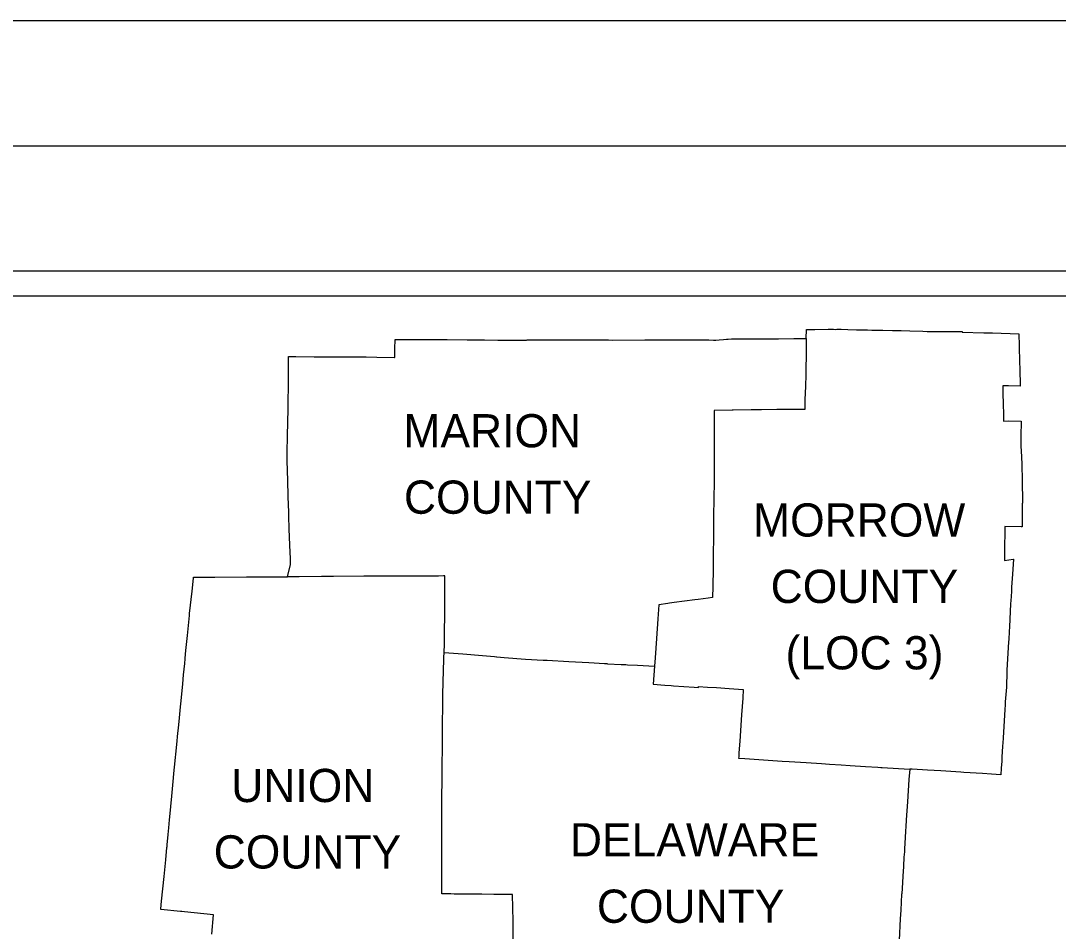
# Model space of a CAD drawing. Extents: x 0 to 34, y 0 to 22.
# Drawn here: x 3.544 to 7.693, y 18.358 to 22 of the extents above; entities that cross this region are included whole.
import ezdxf

# ---------------------------------------------------------------- set-up
doc = ezdxf.new("R2010")
doc.units = 0
for name, color, linetype in [('GM_X_County', 7, 'Continuous'), ('SH_Border', 7, 'Continuous'), ('SH_Cut_Line', 7, 'Continuous'), ('SH_Data', 7, 'Continuous')]:
    doc.layers.add(name, color=color, linetype=linetype)

msp = doc.modelspace()

# ---------------------------------------------------------------- linework, layer by layer
at = {"layer": 'GM_X_County'}
for p, q in [((6.6856, 20.7295), (6.6866, 20.7654)), ((6.6866, 20.7654), (6.7195, 20.7656)), ((6.7195, 20.7656), (6.7729, 20.7658)), ((6.7729, 20.7658), (6.7945, 20.7658)), ((6.7945, 20.7658), (6.803, 20.7656)), ((6.803, 20.7656), (6.8079, 20.7658)), ((6.8079, 20.7658), (6.8254, 20.766)), ((6.8254, 20.766), (6.8515, 20.7651)), ((6.8515, 20.7651), (6.886, 20.7639)), ((6.886, 20.7639), (6.8953, 20.7638)), ((6.8953, 20.7638), (6.9269, 20.7633)), ((6.9269, 20.7633), (6.9307, 20.7631)), ((6.9307, 20.7631), (6.9473, 20.7629)), ((6.9473, 20.7629), (6.9532, 20.7628)), ((6.9532, 20.7628), (6.9634, 20.7628)), ((6.9634, 20.7628), (6.9922, 20.7622)), ((6.9922, 20.7622), (7.0299, 20.7614)), ((7.0299, 20.7614), (7.0649, 20.7604)), ((7.0649, 20.7604), (7.1, 20.7596)), ((7.1, 20.7596), (7.1524, 20.7582)), ((7.1524, 20.7582), (7.1695, 20.7575)), ((7.1695, 20.7575), (7.1866, 20.7571)), ((7.1866, 20.7571), (7.2147, 20.7565)), ((7.2147, 20.7565), (7.3093, 20.7565)), ((7.3093, 20.7565), (7.3093, 20.7542)), ((7.3093, 20.7542), (7.3951, 20.752)), ((7.3951, 20.752), (7.4302, 20.7511)), ((7.4302, 20.7511), (7.5362, 20.7483)), ((7.5362, 20.7483), (7.5371, 20.6992)), ((5.0405, 20.6879), (5.0411, 20.725)), ((5.0411, 20.725), (5.0621, 20.7251)), ((5.0621, 20.7251), (5.1848, 20.725)), ((5.1848, 20.725), (5.2501, 20.7247)), ((5.2501, 20.7247), (5.329, 20.7243)), ((5.329, 20.7243), (5.3818, 20.7231)), ((5.3818, 20.7231), (5.3901, 20.7232)), ((5.3901, 20.7232), (5.3993, 20.723)), ((5.3993, 20.723), (5.4521, 20.7223)), ((5.4521, 20.7223), (5.4693, 20.7224)), ((5.4693, 20.7224), (5.5416, 20.7227)), ((5.5416, 20.7227), (5.567, 20.7229)), ((5.567, 20.7229), (5.5697, 20.723)), ((5.5697, 20.723), (5.5794, 20.7231)), ((5.5794, 20.7231), (5.6115, 20.7233)), ((5.6115, 20.7233), (5.6401, 20.7234)), ((5.6401, 20.7234), (5.6827, 20.7237)), ((5.6827, 20.7237), (5.753, 20.724)), ((5.753, 20.724), (5.8235, 20.7233)), ((5.8235, 20.7233), (5.8261, 20.7233)), ((5.8261, 20.7233), (5.8298, 20.7232)), ((5.8298, 20.7232), (5.8419, 20.7232)), ((5.8419, 20.7232), (5.8941, 20.7231)), ((5.8941, 20.7231), (5.9122, 20.7229)), ((5.9122, 20.7229), (6.0406, 20.7231)), ((6.0406, 20.7231), (6.1476, 20.7233)), ((6.1476, 20.7233), (6.2484, 20.7238)), ((6.2484, 20.7238), (6.2963, 20.723)), ((6.2963, 20.723), (6.3143, 20.7226)), ((6.3143, 20.7226), (6.3191, 20.7226)), ((6.3191, 20.7226), (6.3236, 20.7228)), ((6.3236, 20.7228), (6.3375, 20.7237)), ((6.3375, 20.7237), (6.3545, 20.725)), ((6.3545, 20.725), (6.3662, 20.7259)), ((6.3662, 20.7259), (6.3728, 20.7263)), ((6.3728, 20.7263), (6.3872, 20.7275)), ((6.3872, 20.7275), (6.3891, 20.7276)), ((6.3891, 20.7276), (6.4254, 20.7277)), ((6.4254, 20.7277), (6.4621, 20.7274)), ((6.4621, 20.7274), (6.4892, 20.7279)), ((6.4892, 20.7279), (6.4913, 20.728)), ((6.4913, 20.728), (6.4973, 20.728)), ((6.4973, 20.728), (6.5516, 20.7282)), ((6.5516, 20.7282), (6.5752, 20.7283)), ((6.5752, 20.7283), (6.6354, 20.7289)), ((6.6354, 20.7289), (6.6595, 20.7292)), ((6.6595, 20.7292), (6.6856, 20.7295)), ((6.6856, 20.7295), (6.6853, 20.6951)), ((5.04, 20.6537), (5.0405, 20.6879)), ((6.6853, 20.6951), (6.6847, 20.6432)), ((7.5371, 20.6992), (7.5389, 20.6325)), ((4.6151, 20.6558), (4.6152, 20.6569)), ((4.6151, 20.652), (4.6151, 20.6558)), ((4.6153, 20.6358), (4.6151, 20.652)), ((4.6152, 20.6569), (4.6438, 20.6567)), ((4.6152, 20.5873), (4.6153, 20.6358)), ((4.6438, 20.6567), (4.7179, 20.6562)), ((4.7179, 20.6562), (4.7573, 20.656)), ((4.7573, 20.656), (4.8279, 20.656)), ((4.8279, 20.656), (4.899, 20.6556)), ((4.899, 20.6556), (4.9257, 20.6554)), ((4.9257, 20.6554), (4.9685, 20.6545)), ((4.9685, 20.6545), (5.0394, 20.6529)), ((5.0394, 20.6529), (5.04, 20.6529)), ((5.04, 20.6529), (5.04, 20.6537)), ((6.6845, 20.6263), (6.6841, 20.5852)), ((6.6847, 20.6432), (6.6845, 20.6263)), ((7.5389, 20.6325), (7.5396, 20.6085)), ((4.6149, 20.534), (4.6152, 20.5873)), ((6.6841, 20.5823), (6.6829, 20.5394)), ((6.6841, 20.5852), (6.6841, 20.5823)), ((7.5396, 20.6085), (7.5412, 20.5388)), ((6.6829, 20.5394), (6.6828, 20.5379)), ((7.4947, 20.5397), (7.4719, 20.5401)), ((7.4719, 20.5401), (7.4724, 20.5242)), ((7.5412, 20.5388), (7.4947, 20.5397)), ((4.6142, 20.4815), (4.6149, 20.534)), ((6.6828, 20.5379), (6.6796, 20.4842)), ((7.4724, 20.5242), (7.4722, 20.5102)), ((7.4722, 20.5102), (7.4722, 20.5091)), ((7.4722, 20.5091), (7.4731, 20.4672)), ((4.6134, 20.4465), (4.6142, 20.4815)), ((6.6796, 20.4842), (6.6794, 20.4454)), ((7.4731, 20.4672), (7.474, 20.4249)), ((4.6106, 20.3414), (4.6134, 20.4465)), ((6.3888, 20.4424), (6.3171, 20.441)), ((6.3171, 20.441), (6.3172, 20.4059)), ((6.3927, 20.4425), (6.3888, 20.4424)), ((6.4647, 20.4432), (6.3927, 20.4425)), ((6.4769, 20.4434), (6.4647, 20.4432)), ((6.482, 20.4435), (6.4769, 20.4434)), ((6.5063, 20.444), (6.482, 20.4435)), ((6.5685, 20.4447), (6.5063, 20.444)), ((6.603, 20.4451), (6.5685, 20.4447)), ((6.6383, 20.4454), (6.603, 20.4451)), ((6.6794, 20.4454), (6.6383, 20.4454)), ((7.474, 20.4249), (7.4745, 20.3989)), ((6.3172, 20.4059), (6.3172, 20.3947)), ((6.3172, 20.3947), (6.3173, 20.3712)), ((7.4745, 20.3989), (7.4952, 20.3991)), ((7.4952, 20.3991), (7.5454, 20.3989)), ((7.5454, 20.3989), (7.5444, 20.3365)), ((4.6101, 20.2718), (4.6106, 20.3414)), ((6.3173, 20.3435), (6.3172, 20.2998)), ((6.3173, 20.3712), (6.3173, 20.3435)), ((7.5444, 20.3365), (7.5443, 20.3345)), ((7.5443, 20.3345), (7.5443, 20.3204)), ((6.3172, 20.2998), (6.317, 20.2299)), ((7.5443, 20.3204), (7.5444, 20.2979)), ((7.5444, 20.2979), (7.5459, 20.2576)), ((4.61, 20.2358), (4.6101, 20.2708)), ((4.6101, 20.2708), (4.6101, 20.2718)), ((7.5459, 20.2576), (7.5473, 20.2239)), ((4.6104, 20.2048), (4.61, 20.2358)), ((6.317, 20.2299), (6.3168, 20.1568)), ((7.5473, 20.2239), (7.5487, 20.1629)), ((4.6137, 20.1056), (4.6104, 20.2048)), ((6.3168, 20.1568), (6.3153, 20.0187)), ((7.5487, 20.1629), (7.549, 20.153)), ((7.549, 20.153), (7.5507, 20.0826)), ((4.6143, 20.0864), (4.6137, 20.1056)), ((4.6146, 20.0742), (4.6143, 20.0864)), ((7.5507, 20.0826), (7.5508, 20.079)), ((4.6147, 20.073), (4.6146, 20.0742)), ((4.6159, 20.0266), (4.6147, 20.073)), ((7.5496, 20.0597), (7.5495, 20.0116)), ((7.5499, 20.0717), (7.5496, 20.0678)), ((7.5496, 20.0678), (7.5496, 20.0631)), ((7.5496, 20.0631), (7.5496, 20.0597)), ((7.55, 20.0727), (7.5499, 20.0717)), ((7.5503, 20.0735), (7.55, 20.0727)), ((7.5506, 20.074), (7.5503, 20.0735)), ((7.5508, 20.079), (7.5506, 20.074)), ((4.616, 20.0228), (4.6159, 20.0266)), ((4.6162, 20.0178), (4.616, 20.0228)), ((4.6179, 19.9678), (4.6162, 20.0178)), ((6.3153, 20.0187), (6.3146, 19.9478)), ((7.5495, 20.0116), (7.5497, 19.9808)), ((4.6203, 19.902), (4.6179, 19.9678)), ((7.5453, 19.9759), (7.4791, 19.9766)), ((7.4791, 19.9766), (7.4791, 19.9708)), ((7.4791, 19.9708), (7.4791, 19.945)), ((7.5497, 19.9759), (7.5453, 19.9759)), ((7.5497, 19.9808), (7.5497, 19.9759)), ((6.3146, 19.9478), (6.3135, 19.8521)), ((7.4791, 19.945), (7.479, 19.9046)), ((4.6225, 19.8473), (4.6203, 19.902)), ((7.479, 19.9046), (7.4788, 19.8413)), ((4.6234, 19.8253), (4.6225, 19.8473)), ((6.3135, 19.8521), (6.3128, 19.8072)), ((7.4788, 19.8413), (7.5127, 19.8457)), ((7.5145, 19.8458), (7.5105, 19.7867)), ((7.5127, 19.8457), (7.5145, 19.8458)), ((4.6114, 19.7761), (4.6234, 19.8253)), ((6.3128, 19.8072), (6.3116, 19.737)), ((4.2291, 19.7189), (4.2348, 19.7709)), ((4.2348, 19.7709), (4.2352, 19.7745)), ((4.2352, 19.7745), (4.2355, 19.7745)), ((4.2355, 19.7745), (4.3101, 19.7744)), ((4.3101, 19.7744), (4.3201, 19.7745)), ((4.3201, 19.7745), (4.4466, 19.7751)), ((4.4466, 19.7751), (4.4939, 19.7753)), ((4.4939, 19.7753), (4.5443, 19.7756)), ((4.5443, 19.7756), (4.6114, 19.7761)), ((4.6572, 19.7763), (4.6114, 19.7761)), ((4.7464, 19.7766), (4.6572, 19.7763)), ((4.7722, 19.7767), (4.7464, 19.7766)), ((4.7947, 19.7769), (4.7722, 19.7767)), ((4.9158, 19.7778), (4.7947, 19.7769)), ((4.9688, 19.778), (4.9158, 19.7778)), ((5.0125, 19.7781), (4.9688, 19.778)), ((5.085, 19.7785), (5.0125, 19.7781)), ((5.1554, 19.7788), (5.085, 19.7785)), ((5.2154, 19.779), (5.1554, 19.7788)), ((5.2346, 19.7791), (5.2154, 19.779)), ((5.2402, 19.7791), (5.2346, 19.7791)), ((5.2403, 19.7489), (5.2402, 19.7791)), ((7.5105, 19.7867), (7.5068, 19.7342)), ((4.2193, 19.6292), (4.2291, 19.7189)), ((5.2399, 19.6563), (5.2402, 19.7186)), ((5.2402, 19.7186), (5.2403, 19.7452)), ((5.2403, 19.7452), (5.2403, 19.7489)), ((6.3116, 19.737), (6.3106, 19.6928)), ((7.5059, 19.7185), (7.5047, 19.697)), ((7.5068, 19.7342), (7.5059, 19.7185)), ((6.1326, 19.6689), (6.0957, 19.6636)), ((6.1384, 19.6697), (6.1326, 19.6689)), ((6.1578, 19.6725), (6.1384, 19.6697)), ((6.2406, 19.6837), (6.1578, 19.6725)), ((6.2538, 19.6854), (6.2406, 19.6837)), ((6.2938, 19.6906), (6.2538, 19.6854)), ((6.3106, 19.6928), (6.2938, 19.6906)), ((7.503, 19.6673), (7.4982, 19.5761)), ((7.5038, 19.6809), (7.503, 19.6673)), ((7.5047, 19.697), (7.5038, 19.6809)), ((4.2184, 19.6213), (4.2193, 19.6292)), ((5.2396, 19.6128), (5.2399, 19.6563)), ((6.0957, 19.6636), (6.0918, 19.6072)), ((4.2107, 19.5404), (4.2184, 19.6213)), ((5.2392, 19.5669), (5.2396, 19.6128)), ((6.0918, 19.6072), (6.0864, 19.5285)), ((5.2387, 19.5275), (5.2392, 19.5669)), ((7.4968, 19.5568), (7.4952, 19.5252)), ((7.4982, 19.5761), (7.4968, 19.5568)), ((4.2062, 19.4936), (4.2107, 19.5404)), ((5.2376, 19.4736), (5.2383, 19.5069)), ((5.2383, 19.5069), (5.2387, 19.5275)), ((6.0864, 19.5285), (6.0811, 19.4514)), ((7.4948, 19.5152), (7.4884, 19.4028)), ((7.4952, 19.5252), (7.4948, 19.5152)), ((4.2017, 19.4482), (4.2036, 19.4675)), ((4.2036, 19.4675), (4.2062, 19.4936)), ((5.2365, 19.4529), (5.2376, 19.4736)), ((5.2376, 19.4736), (5.3126, 19.4675)), ((5.3126, 19.4675), (5.3905, 19.4609)), ((5.3905, 19.4609), (5.4384, 19.4564)), ((4.1954, 19.3831), (4.1998, 19.4294)), ((4.1998, 19.4294), (4.2017, 19.4482)), ((5.2339, 19.3538), (5.2364, 19.4466)), ((5.2364, 19.4466), (5.2365, 19.4529)), ((5.4384, 19.4564), (5.4467, 19.4555)), ((5.4467, 19.4555), (5.4485, 19.4552)), ((5.4485, 19.4552), (5.4774, 19.4526)), ((5.4774, 19.4526), (5.5631, 19.4467)), ((5.5631, 19.4467), (5.6333, 19.4427)), ((5.6333, 19.4427), (5.6494, 19.4423)), ((5.6494, 19.4423), (5.7358, 19.4364)), ((5.7358, 19.4364), (5.8157, 19.4328)), ((5.8157, 19.4328), (5.8793, 19.429)), ((5.8793, 19.429), (5.8884, 19.4285)), ((5.8884, 19.4285), (5.8912, 19.4283)), ((5.8912, 19.4283), (5.9457, 19.4256)), ((5.9457, 19.4256), (5.9494, 19.4255)), ((5.9494, 19.4255), (5.9579, 19.4251)), ((5.9579, 19.4251), (5.9644, 19.4247)), ((5.9644, 19.4247), (5.9711, 19.4243)), ((5.9711, 19.4243), (6.0105, 19.4222)), ((6.0105, 19.4222), (6.0789, 19.4187)), ((6.0789, 19.4187), (6.0739, 19.3459)), ((6.0811, 19.4514), (6.0789, 19.4187)), ((4.1919, 19.3474), (4.1954, 19.3831)), ((7.488, 19.3953), (7.4858, 19.3354)), ((7.4884, 19.4028), (7.488, 19.3953)), ((4.1853, 19.2794), (4.1919, 19.3474)), ((5.2327, 19.3073), (5.2338, 19.3517)), ((5.2338, 19.3517), (5.2339, 19.3538)), ((6.0739, 19.3459), (6.1195, 19.3429)), ((6.1195, 19.3429), (6.146, 19.3409)), ((6.146, 19.3409), (6.1542, 19.3402)), ((6.1542, 19.3402), (6.2375, 19.3345)), ((6.2546, 19.3335), (6.255, 19.3369)), ((6.255, 19.3369), (6.2909, 19.3345)), ((7.4858, 19.3354), (7.4858, 19.335)), ((5.232, 19.2738), (5.2327, 19.3073)), ((6.2375, 19.3345), (6.2546, 19.3335)), ((6.2909, 19.3345), (6.3273, 19.3324)), ((6.3273, 19.3324), (6.3779, 19.3287)), ((6.3779, 19.3287), (6.4336, 19.3249)), ((6.4336, 19.3249), (6.4319, 19.2909)), ((7.4858, 19.335), (7.4815, 19.2751)), ((4.1786, 19.2114), (4.1829, 19.2554)), ((4.1829, 19.2554), (4.1853, 19.2794)), ((5.2313, 19.1726), (5.232, 19.2738)), ((6.4319, 19.2909), (6.4268, 19.224)), ((7.4807, 19.2633), (7.4796, 19.2456)), ((7.481, 19.268), (7.4807, 19.2633)), ((7.4815, 19.2751), (7.481, 19.268)), ((4.1745, 19.1699), (4.1786, 19.2114)), ((6.4268, 19.224), (6.4197, 19.1184)), ((7.4796, 19.2456), (7.4729, 19.1318)), ((4.1726, 19.1505), (4.1745, 19.1699)), ((5.2305, 19.14), (5.2313, 19.1726)), ((4.1678, 19.1053), (4.1726, 19.1505)), ((5.2303, 19.1006), (5.2305, 19.14)), ((7.4725, 19.1289), (7.4708, 19.0971)), ((7.4729, 19.1318), (7.4725, 19.1289)), ((4.159, 19.0138), (4.1678, 19.1053)), ((5.2302, 19.0808), (5.2303, 19.1006)), ((6.4197, 19.1184), (6.4165, 19.0718)), ((7.4708, 19.0971), (7.4682, 19.0561)), ((5.229, 19.0331), (5.2302, 19.0808)), ((6.4155, 19.0558), (6.415, 19.0497)), ((6.415, 19.0497), (6.4398, 19.0488)), ((6.4165, 19.0718), (6.4155, 19.0558)), ((6.4398, 19.0488), (6.5888, 19.0388)), ((7.4682, 19.0561), (7.4671, 19.0382)), ((4.1567, 18.9886), (4.159, 19.0138)), ((5.229, 19.0154), (5.229, 19.0331)), ((5.2291, 18.9673), (5.229, 19.0154)), ((6.5888, 19.0388), (6.6174, 19.037)), ((6.6174, 19.037), (6.6855, 19.0326)), ((6.6855, 19.0326), (6.7462, 19.0286)), ((6.7462, 19.0286), (6.7791, 19.0269)), ((6.7791, 19.0269), (6.8256, 19.0237)), ((6.8256, 19.0237), (6.8616, 19.0212)), ((6.8616, 19.0212), (6.922, 19.0176)), ((6.922, 19.0176), (6.9725, 19.0143)), ((6.9725, 19.0143), (6.9844, 19.0136)), ((6.9844, 19.0136), (6.989, 19.0133)), ((6.989, 19.0133), (7.0549, 19.0094)), ((7.0549, 19.0094), (7.0992, 19.0067)), ((7.0992, 19.0067), (7.0963, 18.9644)), ((7.1021, 19.0065), (7.0992, 19.0067)), ((7.1094, 19.0061), (7.1021, 19.0065)), ((7.1699, 19.0024), (7.1094, 19.0061)), ((7.4654, 19.0097), (7.4638, 18.9838)), ((7.4671, 19.0382), (7.4654, 19.0097)), ((4.148, 18.8979), (4.155, 18.9711)), ((4.155, 18.9711), (4.1567, 18.9886)), ((5.229, 18.942), (5.2291, 18.9673)), ((7.0963, 18.9644), (7.0905, 18.8757)), ((7.2243, 18.9992), (7.1699, 19.0024)), ((7.3036, 18.9942), (7.2243, 18.9992)), ((7.3161, 18.9932), (7.3036, 18.9942)), ((7.3901, 18.9884), (7.3161, 18.9932)), ((7.4268, 18.9861), (7.3901, 18.9884)), ((7.4638, 18.9838), (7.4268, 18.9861)), ((5.2288, 18.9137), (5.229, 18.942)), ((4.1405, 18.8162), (4.148, 18.8979)), ((5.2283, 18.8988), (5.2286, 18.9118)), ((5.2283, 18.8529), (5.2283, 18.8988)), ((5.2286, 18.9118), (5.2288, 18.9137)), ((5.2277, 18.6909), (5.2283, 18.8529)), ((7.0905, 18.8757), (7.0857, 18.8037)), ((4.1363, 18.7719), (4.1393, 18.8033)), ((4.1393, 18.8033), (4.1405, 18.8162)), ((7.0856, 18.801), (7.0814, 18.7337)), ((7.0857, 18.8024), (7.0856, 18.801)), ((7.0857, 18.8037), (7.0857, 18.8024)), ((4.1337, 18.7446), (4.1363, 18.7719)), ((4.1297, 18.7031), (4.1337, 18.7446)), ((7.0814, 18.7337), (7.0796, 18.709)), ((4.1239, 18.644), (4.1287, 18.6925)), ((4.1287, 18.6925), (4.1291, 18.6967)), ((4.1291, 18.6967), (4.1297, 18.7031)), ((5.2285, 18.6034), (5.2277, 18.6909)), ((7.0779, 18.6768), (7.077, 18.6635)), ((7.0786, 18.6894), (7.0779, 18.6768)), ((7.0789, 18.6896), (7.0786, 18.6894)), ((7.0796, 18.709), (7.0789, 18.6896)), ((4.1174, 18.5774), (4.1239, 18.644)), ((7.0764, 18.6552), (7.0743, 18.6171)), ((7.077, 18.6635), (7.0764, 18.6552)), ((5.2284, 18.5367), (5.2285, 18.6034)), ((7.0743, 18.6171), (7.0717, 18.5778)), ((4.1076, 18.479), (4.1174, 18.5774)), ((7.0702, 18.5525), (7.0673, 18.5072)), ((7.0717, 18.5778), (7.0702, 18.5525)), ((5.2287, 18.5076), (5.2284, 18.5367)), ((5.2338, 18.5075), (5.2287, 18.5076)), ((5.2638, 18.5073), (5.2338, 18.5075)), ((5.2774, 18.507), (5.2638, 18.5073)), ((5.3044, 18.5069), (5.2774, 18.507)), ((5.3875, 18.5059), (5.3044, 18.5069)), ((5.4364, 18.5055), (5.3875, 18.5059)), ((5.493, 18.5048), (5.4364, 18.5055)), ((7.0671, 18.5057), (7.0637, 18.442)), ((7.0673, 18.5072), (7.0671, 18.5057)), ((4.1046, 18.4478), (4.1076, 18.479)), ((5.5113, 18.5048), (5.493, 18.5048)), ((5.5131, 18.3987), (5.5113, 18.5048)), ((4.1043, 18.4455), (4.1046, 18.4478)), ((4.1836, 18.4371), (4.1043, 18.4455)), ((4.1888, 18.4365), (4.1836, 18.4371)), ((4.1989, 18.4355), (4.1888, 18.4365)), ((4.3146, 18.4234), (4.1989, 18.4355)), ((4.309, 18.3461), (4.3146, 18.4234)), ((7.0637, 18.442), (7.0616, 18.4073)), ((5.5131, 18.3699), (5.5131, 18.3987)), ((7.0616, 18.4073), (7.0567, 18.3217)), ((5.5136, 18.281), (5.5131, 18.3699))]:
    msp.add_line(p, q, dxfattribs=at)
at = {"layer": 'SH_Border'}
msp.add_lwpolyline([(1.5, 21.5), (33.5, 21.5), (33.5, 0.5), (1.5, 0.5)], close=True, dxfattribs=at)
at = {"layer": 'SH_Cut_Line'}
msp.add_lwpolyline([(0, 0), (34, 0), (34, 22), (0, 22)], close=True, dxfattribs=at)
at = {"layer": 'SH_Data'}
for p, q in [((2, 21), (9, 21)), ((2.1, 20.9), (8.9, 20.9))]:
    msp.add_line(p, q, dxfattribs=at)

# ---------------------------------------------------------------- texts
for s, p in [('MARION', (5.0747, 20.2936)), ('COUNTY', (5.0767, 20.028)), ('MORROW', (6.4731, 19.9367)), ('COUNTY', (6.5433, 19.6711)), ('(LOC 3)', (6.6026, 19.4055)), ('UNION', (4.386, 18.8747)), ('DELAWARE', (5.7404, 18.6574)), ('COUNTY', (4.3158, 18.609)), ('COUNTY', (5.8483, 18.3918))]:
    msp.add_text(s, height=0.13282, dxfattribs=at).set_placement(p)

doc.saveas('drawing.dxf')
